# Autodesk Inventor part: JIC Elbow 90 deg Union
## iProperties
Category: Hydraulics
Title: JIC Elbow 90 deg Union
Subject: Hydraulic Adapters
Author: QBZ
Shininess: 27.0
PropertySet Name: _Private Model Information
Created: 2001-03
Part Number: 2039-8-8S
Document SubType Name: Modeling
Designer: QBZ
Material: Steel, Mild
Catalog Web Link: http://www.aeroquip.com
Description: JIC Elbow 90 8-8
Control State: 0
Master: False
Checked Out: False
PropertySet Name: Design Tracking Control
Density: 7.86
Volumn: 11.938033425281926
Area: 60.34729061233818
PropertySet Name: Model Information
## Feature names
1. Body1 [Extrusion]
2. Body2 [Extrusion]
3. Revolution1
4. JIC 1 [Revolution]
5. JIC 2 [Revolution]
6. JIC1 id
7. JIC2 id [Hole]
8. Fillet1
